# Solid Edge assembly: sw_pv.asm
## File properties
Author: Sham
Template: Sync Iso Assembly.asm
Last saved by: Rajat Kamboj
Revision: 7
Application: Solid Edge
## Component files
base.par
Screw.par
moveable jaw.par
handle.par
handle screw.par
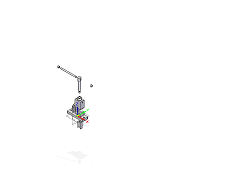
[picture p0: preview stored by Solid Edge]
